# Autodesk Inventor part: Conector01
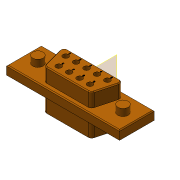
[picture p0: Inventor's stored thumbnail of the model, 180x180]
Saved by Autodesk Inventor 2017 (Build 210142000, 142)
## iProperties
GlobalPropertyList: <PropertyList/>
Created: 2016-09
Part Number: Conector01
Material: PBT Plastic
Document SubType Name: Modeling
Designer: User
Density: 1.31 g/cm^3
Appearance: Orange
Categories: <MemberInstance><Categories><Category DisplayName="" Mnemonic="CABLEANDHARNESS" InternalName="e4a7e005-5e42-4d16-b293-125e7f0d0512"><Category DisplayName="" Mne
Author: User
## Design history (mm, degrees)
sketch "Sketch1"
  geometry: L1 (-17.5, -7.5)-(17.5, -7.5); L2 (17.5, -7.5)-(17.5, 7.5); L3 (17.5, 7.5)-(-17.5, 7.5); L4 (-17.5, 7.5)-(-17.5, -7.5); L5 (-17.5, -7.5)-(17.5, 7.5); L6 (17.5, -7.5)-(-17.5, 7.5); L7 (-17.5, 7.5)-(-13.481, -7.5); L8 (17.5, 7.5)-(13.481, -7.5); L9 (0, 0)-(0, 16.553); L10 (-13.481, -7.5)-(13.481, -7.5)
  constraints: 20 end point, 2 horizontal, 2 midpoint, 2 parallel, 2 point on line, 1 perpendicular, 1 vertical, 1 other
  dimensions: "d0" = 35 distance of L3.end L2.end; "d1" = 15 distance of L2.end L1.end; "d2" = 15 deg angle of L7 L4
extrude "Extrusion1" new body sketch "Sketch1" distance "d3" = 8; taper "d4" = 0 deg
sketch "Sketch2"
  geometry: L1 (-32.5, -10)-(32.5, -10); L2 (32.5, -10)-(32.5, 10); L3 (32.5, 10)-(-32.5, 10); L4 (-32.5, 10)-(-32.5, -10); L5 (-32.5, -10)-(32.5, 10); L6 (32.5, -10)-(-32.5, 10); 1 further point
  constraints: 12 end point, 2 midpoint, 2 parallel, 1 horizontal, 1 perpendicular
  dimensions: "d5" = 65 distance of L3.end L2.end; "d6" = 20 distance of L2.end L1.end
extrude "Extrusion2" join sketch "Sketch2" distance "d7" = 5; taper "d8" = 0 deg
sketch "Sketch3"
  geometry: L1 (-32.5, -10)-(-32.5, 10) reference; L2 (32.5, 10)-(32.5, -10) reference; C1 r 3 at (-24.5, 0); C2 r 3 at (24.5, 0); 1 further point
  constraints: 2 centre point
  dimensions: "d9" = 6 diameter of C1; "d10" = 8 distance from line of L1 C1.centre; "d11" = 6 diameter of C2; "d12" = 8 distance from line of L2 C2.centre
extrude "Extrusion3" join sketch "Sketch3" distance "d13" = 4; taper "d14" = 0 deg
fillet "Fillet1" dims "d15" = 2
chamfer "Chamfer1" distance "d16" = 0.5; stored, may be unused: second distance "d17" = 2, angle "d18" = 45 deg
chamfer "Chamfer2" distance "d19" = 0.5; stored, may be unused: second distance "d20" = 2, angle "d21" = 45 deg
sketch "Sketch4"
  geometry: 9 further points
  constraints: 7 horizontal alignment, 1 other
hole "Hole1" sketch "Sketch4" at (-12, 3.5), (-6, 3.5), (0, 3.5), (6, 3.5), (12, 3.5), (-9, -3.5), (-3, -3.5), (3, -3.5), (9, -3.5) diameter "d33" = 2; stored, may be unused: countersink angle "d37" = 90 deg, drill point angle "d39" = 118 deg; dims "d34" = 6, "d35" = 3.2, "d36" = 5, "d38" = 8
sketch "Sketch5"
  geometry: L1 (-12.343, 6.335)-(-11.486, 6.335); L2 (-11.486, 6.335)-(-11.486, 5.239); L3 (-11.486, 5.239)-(-12.343, 5.239); L4 (-12.343, 5.239)-(-12.343, 6.335); L5 (-13.395, -5.888)-(-16.342, 5.112) reference; L6 (11.946, -7)-(-11.946, -7) reference; L7 (16.342, 5.112)-(13.395, -5.888) reference; L8 (-14.894, 7)-(14.894, 7) reference; L9 (-6.343, 5.239)-(-6.343, 6.335); L10 (-6.343, 6.335)-(-5.486, 6.335); L11 (-5.486, 6.335)-(-5.486, 5.239); L12 (-5.486, 5.239)-(-6.343, 5.239); L13 (-0.343, 5.239)-(-0.343, 6.335); L14 (-0.343, 6.335)-(0.514, 6.335); L15 (0.514, 6.335)-(0.514, 5.239); L16 (0.514, 5.239)-(-0.343, 5.239); L17 (5.657, 5.239)-(5.657, 6.335); L18 (5.657, 6.335)-(6.514, 6.335); L19 (6.514, 6.335)-(6.514, 5.239); L20 (6.514, 5.239)-(5.657, 5.239); L21 (11.657, 5.239)-(11.657, 6.335); L22 (11.657, 6.335)-(12.514, 6.335); L23 (12.514, 6.335)-(12.514, 5.239); L24 (12.514, 5.239)-(11.657, 5.239); L25 (-9.343, -1.761)-(-9.343, -0.665); L26 (-9.343, -0.665)-(-8.486, -0.665); L27 (-8.486, -0.665)-(-8.486, -1.761); L28 (-8.486, -1.761)-(-9.343, -1.761); L29 (-3.343, -1.761)-(-3.343, -0.665); L30 (-3.343, -0.665)-(-2.486, -0.665); L31 (-2.486, -0.665)-(-2.486, -1.761); L32 (-2.486, -1.761)-(-3.343, -1.761); L33 (2.657, -1.761)-(2.657, -0.665); L34 (2.657, -0.665)-(3.514, -0.665); L35 (3.514, -0.665)-(3.514, -1.761); L36 (3.514, -1.761)-(2.657, -1.761); L37 (8.657, -1.761)-(8.657, -0.665); L38 (8.657, -0.665)-(9.514, -0.665); L39 (9.514, -0.665)-(9.514, -1.761); L40 (9.514, -1.761)-(8.657, -1.761); C1 r 1.6 at (3, -3.5) reference; C2 r 1.6 at (-9, -3.5) reference; C3 r 1.6 at (6, 3.5) reference; C4 r 1.6 at (-6, 3.5) reference; C5 r 1.6 at (-12, 3.5) reference; C6 r 1.6 at (0, 3.5) reference; C7 r 1.6 at (12, 3.5) reference; C8 r 1.6 at (-3, -3.5) reference; C9 r 1.6 at (9, -3.5) reference; A1 r 1.5 centre (-11.946, -5.5) between (-13.395, -5.888) and (-11.946, -7) reference; A2 r 1.5 centre (11.946, -5.5) between (11.946, -7) and (13.395, -5.888) reference; A3 r 1.5 centre (14.894, 5.5) between (16.342, 5.112) and (14.894, 7) reference; A4 r 1.5 centre (-14.894, 5.5) between (-14.894, 7) and (-16.342, 5.112) reference; 1 further point
  constraints: 18 other
extrude "Extrusion4" join sketch "Sketch5" distance "d40" = 0.2; taper "d41" = 0 deg
sketch "Sketch15"
  geometry: L1 (11.946, -7.5)-(-11.946, -7.5) reference; L2 (16.825, 4.982)-(13.878, -6.018) reference; L3 (-14.894, 7.5)-(14.894, 7.5) reference; L4 (-13.878, -6.018)-(-16.825, 4.982) reference; L5 (32, 9.5)-(-32, 9.5) reference; L6 (32, -9.5)-(32, 9.5) reference; L7 (-32, -9.5)-(32, -9.5) reference; L8 (-32, 9.5)-(-32, -9.5) reference; C1 r 3 at (-24.5, 0) reference; C2 r 3 at (24.5, 0) reference; A1 r 2 centre (11.946, -5.5) between (11.946, -7.5) and (13.878, -6.018) reference; A2 r 2 centre (14.894, 5.5) between (16.825, 4.982) and (14.894, 7.5) reference; A3 r 2 centre (-14.894, 5.5) between (-14.894, 7.5) and (-16.825, 4.982) reference; A4 r 2 centre (-11.946, -5.5) between (-13.878, -6.018) and (-11.946, -7.5) reference; 1 further point
extrude "Extrusion5" join sketch "Sketch15" distance "d42" = 10; taper "d43" = 0 deg
workplane "Work Plane1"
sketch "Sketch16"
  geometry: C1 r 1.6 at (-12, 3.5) reference
sketch "Sketch17"
  geometry: C1 r 1.6 at (-12, 3.5) reference
body "Solid1"
node "Projected Loop1"
node "Projected Loop2"
